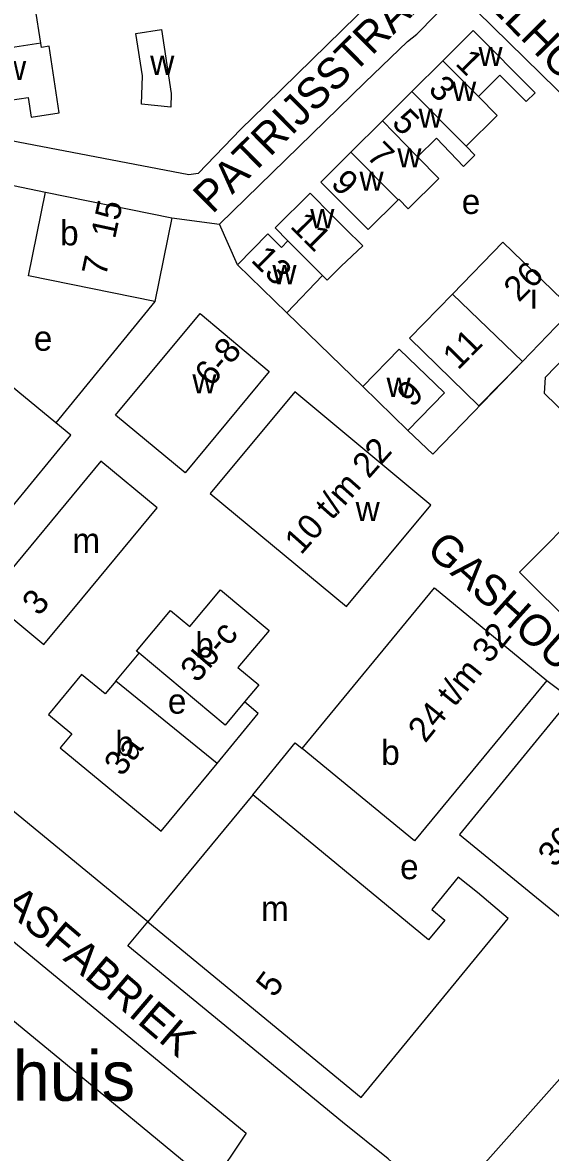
# Model space of a CAD drawing. Extents: x 161775 to 163181, y 382878 to 383925.
# Drawn here: x 162004.9 to 162089.5, y 383208.3 to 383389.4 of the extents above; entities that cross this region are included whole.
import ezdxf

# ---------------------------------------------------------------- set-up
doc = ezdxf.new("R2010")
doc.units = 0
for name, color, linetype in [('BLT_Basislijn', 7, 'Continuous'), ('BLT_Bebouwing', 7, 'Continuous'), ('BLT_Bebouwing_beschrifting', 7, 'Continuous'), ('BLT_Centroide', 7, 'Continuous'), ('BLT_Huisnummer', 7, 'Continuous'), ('BLT_Huisnummer_ tussenligend', 7, 'Continuous'), ('BLT_Huisnummer_reeks', 7, 'Continuous'), ('BLT_Huisnummer_zonder_bebouwing', 7, 'Continuous'), ('BLT_Onderverdeling_panden', 7, 'Continuous'), ('BLT_Plantopo', 7, 'Continuous'), ('BLT_Straatnaam', 7, 'Continuous')]:
    doc.layers.add(name, color=color, linetype=linetype)

msp = doc.modelspace()

# ---------------------------------------------------------------- linework, layer by layer
at = {"layer": 'BLT_Basislijn'}
for p, q in [((162000.79, 383363.85), (162008.6, 383362.24)), ((162028.88, 383358.13), (162036.52, 383357.08)), ((162039.38, 383350.58), (162036.52, 383357.08)), ((162026.15, 383344.72), (162010.27, 383325.26)), ((162019.88, 383283.87), (162023.62, 383288.35)), ((162088.99, 383283.99), (162092.82, 383281.08)), ((162025.01, 383245.29), (161986.24, 383277.16)), ((162118.59, 383251.19), (162072.53, 383199.31))]:
    msp.add_line(p, q, dxfattribs=at)
for points in [[(162013.27, 383465.24), (162032.46, 383442.64), (162034.65, 383439.79), (162067.09, 383402.14), (162068.18, 383400.29), (162065.73, 383397.61), (162046.55, 383378.8)], [(162036.52, 383357.08), (162059.8, 383379.79), (162066.65, 383386.36), (162068.12, 383387.55), (162074.17, 383393.72), (162075.21, 383393.82), (162093.13, 383376.16), (162097.9, 383371.1)], [(162046.55, 383378.8), (162043.75, 383376.06)], [(162043.75, 383376.06), (162039.94, 383372.32), (162033.1, 383365.24), (162031.58, 383365.02), (161990.51, 383372.84)], [(162059.46, 383331.07), (162047.28, 383342.91)], [(162085.05, 383335.1), (162070.72, 383320.25), (162066.71, 383324.02)], [(162036.13, 383270.65), (162042.72, 383278.68), (162040.52, 383280.52)], [(162041.83, 383265.65), (162048.63, 383273.98), (162049.77, 383273.05)], [(161967.44, 383258.8), (161974.67, 383265.82), (162040.76, 383211.42), (162035.26, 383203.21)], [(162072.53, 383199.31), (162063.57, 383207.3), (162056.2, 383213.19), (162021.83, 383241.43), (162025.01, 383245.29)]]:
    msp.add_lwpolyline(points, dxfattribs=at)
at = {"layer": 'BLT_Bebouwing'}
for p, q in [((162072.32, 383383.29), (162067.34, 383378.35)), ((162067.34, 383378.35), (162062.64, 383373.67)), ((162078.01, 383377.56), (162081.04, 383374.52)), ((162062.64, 383373.67), (162057.57, 383368.64)), ((162081.04, 383374.52), (162076.06, 383369.57)), ((162057.57, 383368.64), (162052.75, 383363.85)), ((162077.45, 383368.16), (162076.06, 383369.57)), ((162008.6, 383362.24), (162028.88, 383358.13)), ((162045.42, 383356.51), (162051.04, 383362.09)), ((162028.88, 383358.13), (162026.15, 383344.72)), ((162073.88, 383345.89), (162081.91, 383354.21)), ((162081.91, 383354.21), (162093.09, 383343.41)), ((162085.05, 383335.1), (162073.88, 383345.89)), ((162093.09, 383343.41), (162085.05, 383335.1)), ((162049.77, 383273.05), (162070.95, 383298.82)), ((162070.95, 383298.82), (162088.99, 383283.99)), ((162023.62, 383288.35), (162023.21, 383288.69)), ((162036.13, 383270.65), (162019.88, 383283.87)), ((162042.81, 383283.26), (162040.52, 383280.52)), ((162027.18, 383259.81), (162036.13, 383270.65)), ((162041.83, 383265.65), (162025.01, 383245.29)), ((162025.01, 383245.29), (162059.19, 383217.12)), ((162059.19, 383217.12), (162082.8, 383245.84)), ((162035.26, 383203.21), (162010.9, 383223.27))]:
    msp.add_line(p, q, dxfattribs=at)
for points in [[(162007.87, 383386.1), (162006.99, 383391.88), (162005.69, 383392.74), (162003.6, 383392.42), (162003.39, 383393.81), (162000, 383393.3), (161996.63, 383392.79), (161996.8, 383391.67), (161993.25, 383391.13), (161993.6, 383388.79), (161992.03, 383388.55), (161992.75, 383383.82)], [(162078.01, 383377.56), (162081.45, 383380.97), (162085.66, 383376.73), (162087.1, 383378.16), (162077.19, 383388.13), (162072.32, 383383.29)], [(161992.75, 383383.82), (161993.48, 383378.95), (161995.09, 383379.2), (161995.46, 383376.74), (161999.01, 383377.27), (161999.14, 383376.41), (162000, 383376.54), (162005.86, 383377.41), (162006.33, 383374.27), (162010.81, 383374.95), (162009.2, 383385.6), (162007.97, 383385.42), (162007.87, 383386.1)], [(162077.45, 383368.16), (162075.64, 383366.36), (162071.28, 383370.9), (162068.26, 383367.9)], [(162068.26, 383367.9), (162071.66, 383364.41), (162066.76, 383359.55), (162065.23, 383361.1), (162065.15, 383361.02)], [(162010.27, 383325.26), (161994.08, 383338.56), (161994.76, 383341.1), (161995.6, 383340.88), (161997.08, 383345.43), (161998.36, 383349.91), (161999.45, 383354.44), (162000.37, 383359.11), (161999.61, 383359.28), (162000.79, 383363.85)], [(162052.75, 383363.85), (162056.24, 383360.34), (162060.32, 383356.23), (162065.15, 383361.02)], [(162026.15, 383344.72), (162005.89, 383348.84), (162008.6, 383362.24)], [(162051.04, 383362.09), (162054.54, 383358.55), (162056.67, 383356.42), (162059.46, 383353.61), (162056.02, 383350.34), (162053.77, 383348.1)], [(162047.48, 383354.43), (162046.45, 383353.37), (162044.23, 383355.54), (162039.38, 383350.58)], [(162047.48, 383354.43), (162045.42, 383356.51)], [(162039.38, 383350.58), (162047.28, 383342.91)], [(162047.28, 383342.91), (162053.02, 383348.86)], [(162053.77, 383348.1), (162053.02, 383348.86)], [(162098.23, 383320.61), (162088.59, 383329.95), (162088.78, 383332.59), (162104.91, 383349.23)], [(162033.41, 383342.8), (162044.49, 383333.5), (162031.02, 383317.24), (162019.83, 383326.48), (162033.41, 383342.8)], [(162065.31, 383337.09), (162059.46, 383331.07)], [(162072.59, 383330.05), (162065.31, 383337.09)], [(162059.46, 383331.07), (162066.71, 383324.02)], [(162066.71, 383324.02), (162072.59, 383330.05)], [(161993.14, 383311.01), (161998.72, 383306.36), (162000, 383307.92), (162012.67, 383323.29), (162010.27, 383325.26)], [(161999.32, 383297.19), (162008.33, 383289.71), (162009.37, 383290.96), (162013.14, 383295.52), (162026.52, 383311.61), (162017.51, 383319.1), (161999.32, 383297.19)], [(162113.79, 383294.87), (162095.85, 383312.66), (162084.57, 383301.31), (162102.48, 383283.52), (162104.26, 383285.33)], [(162023.21, 383288.69), (162028.66, 383295.21), (162031.78, 383292.61), (162036.69, 383298.49), (162044.45, 383292), (162039.47, 383286.05), (162042.81, 383283.26)], [(162040.52, 383280.52), (162037.42, 383276.81), (162023.62, 383288.35)], [(162019.88, 383283.87), (162018.17, 383281.81), (162014.38, 383284.91), (162009.11, 383278.49)], [(162088.99, 383283.99), (162067.79, 383258.29), (162049.77, 383273.05)], [(162092.82, 383281.08), (162074.98, 383259.26), (162100.5, 383238.38), (162112.07, 383252.52), (162108.1, 383255.76), (162114.38, 383263.45)], [(162009.11, 383278.49), (162012.84, 383275.43), (162010.96, 383273.18), (162027.18, 383259.81)], [(162074.76, 383252.45), (162070.53, 383247.29), (162072.62, 383245.55), (162070.01, 383242.38), (162041.83, 383265.65)], [(162082.8, 383245.84), (162077.86, 383250), (162074.76, 383252.45)], [(162010.9, 383223.27), (162000, 383232.2), (161997.49, 383234.26)]]:
    msp.add_lwpolyline(points, dxfattribs=at)
for points in [[(162023.12, 383387.65), (162027.19, 383388.27), (162028.78, 383378.06), (162028.71, 383375.86), (162024, 383376.32), (162024.15, 383380.85)], [(162048.59, 383330.21), (162035.03, 383313.95), (162056.85, 383295.8), (162070.39, 383312.06)]]:
    msp.add_lwpolyline(points, close=True, dxfattribs=at)
at = {"layer": 'BLT_Onderverdeling_panden'}
for p, q in [((162007.87, 383386.1), (161992.75, 383383.82)), ((162078.01, 383377.56), (162072.32, 383383.29)), ((162076.06, 383369.57), (162067.34, 383378.35)), ((162068.26, 383367.9), (162062.64, 383373.67)), ((162065.15, 383361.02), (162057.57, 383368.64))]:
    msp.add_line(p, q, dxfattribs=at)
msp.add_lwpolyline([(162053.02, 383348.86), (162047.48, 383354.43)], dxfattribs=at)
at = {"layer": 'BLT_Plantopo'}
msp.add_lwpolyline([(162073.88, 383345.89), (162073.88, 383345.89), (162066.98, 383338.85), (162078.09, 383327.96), (162078.09, 383327.96), (162085.05, 383335.1), (162085.05, 383335.1)], dxfattribs=at)

# ---------------------------------------------------------------- texts
at = {"layer": 'BLT_Bebouwing_beschrifting'}
msp.add_text('Erfgoedhuis', height=8, rotation=359.9999, dxfattribs=at).set_placement((161965.89, 383216.61))
at = {"layer": 'BLT_Centroide'}
for s, p in [('w', (162078.02, 383382.44)), ('w', (162001.66, 383380.19)), ('w', (162025.4, 383381.01)), ('w', (162073.78, 383376.84)), ('w', (162068.41, 383372.56)), ('w', (162065.02, 383366.19)), ('w', (162058.95, 383362.44)), ('e', (162075.34, 383358.73)), ('w', (162051.05, 383356.45)), ('b', (162010.96, 383353.7)), ('w', (162044.99, 383347.48)), ('i', (162086.29, 383343.55)), ('e', (162006.74, 383336.81)), ('w', (162032.16, 383329.97)), ('w', (162063.29, 383329.41)), ('w', (162058.33, 383309.5)), ('m', (162012.92, 383304.41)), ('b', (162032.63, 383287.66)), ('e', (162028.23, 383278.65)), ('b', (162019.8, 383271.89)), ('b', (162062.43, 383270.45)), ('e', (162065.45, 383252.12)), ('m', (162043.16, 383245.44))]:
    msp.add_text(s, height=4, dxfattribs=at).set_placement(p)
at = {"layer": 'BLT_Huisnummer'}
for s, rotation, p in [('1', 314.8044, (162074.15, 383382.73)), ('5', 314.812, (162063.95, 383373.16)), ('9', 314.8282, (162054.18, 383363.44)), ('11', 314.8136, (162047.67, 383356.65)), ('13', 315.4014, (162041.41, 383351.21)), ('26', 45.4014, (162084.51, 383344.46)), ('9', 45.4014, (162067.42, 383327.57)), ('3', 49.4013, (162007.56, 383294.15)), ('3a', 53.4013, (162020.9, 383268.43)), ('5', 53.4013, (162045.26, 383233))]:
    msp.add_text(s, height=4, rotation=rotation, dxfattribs=at).set_placement(p)
at = {"layer": 'BLT_Huisnummer_ tussenligend'}
for s, rotation, p in [('3', 314.8044, (162069.81, 383378.52)), ('7', 314.812, (162059.91, 383367.88))]:
    msp.add_text(s, height=4, rotation=rotation, dxfattribs=at).set_placement(p)
at = {"layer": 'BLT_Huisnummer_reeks'}
for s, rotation, p in [('15', 77.8282, (162019.76, 383354.62)), ('7', 77.8282, (162018.29, 383348.59)), ('6-8', 49.4013, (162035.21, 383330.87)), ('10 t/m 22', 48.4146, (162049.57, 383303.96)), ('3b-c', 49.4013, (162032.92, 383283.44)), ('24 t/m 32', 51, (162069.48, 383273.81)), ('36-a t/m d', 51, (162090.3, 383253.85))]:
    msp.add_text(s, height=4, rotation=rotation, dxfattribs=at).set_placement(p)
at = {"layer": 'BLT_Huisnummer_zonder_bebouwing'}
msp.add_text('11', height=4, rotation=45.4014, dxfattribs=at).set_placement((162074.74, 383333.59))
at = {"layer": 'BLT_Straatnaam'}
for s, rotation, p in [('DOMMELHOEFSTRAAT', 314.5461, (162063.96, 383407.85)), ('PATRIJSSTRAAT', 44.7741, (162035.36, 383358.61)), ('GASHOUDER', 318.0001, (162069.45, 383304.59)), ('GASFABRIEK', 319.5461, (161997.43, 383251.08))]:
    msp.add_text(s, height=5, rotation=rotation, dxfattribs=at).set_placement(p)

doc.saveas('drawing.dxf')
